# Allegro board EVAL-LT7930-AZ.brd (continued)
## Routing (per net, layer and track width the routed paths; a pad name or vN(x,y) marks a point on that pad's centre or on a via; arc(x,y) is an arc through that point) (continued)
INTVCC_1: length 49.7
  TOP w0.254: U1.9 93.96,164.36 v3(94.36,163.96) ; R25.2 94.53,179.09 94.89,179.09 v3(95,179.2) 95.12,179.07 95.45,179.07 R26.2 ; v3(100.08,169.04) R27.2 ; TP14.1 v3(119.89,171.45)
  TOP w0.381: C21.1 v3(94.36,163.96)
  LAYER_6 w0.254: v3(94.36,163.96) 95.38,164.97 96.27,164.97 96.52,165.23 96.52,167.26 ; v3(95,179.2) 95.63,178.56 95.95,178.56 96.52,177.99 96.52,167.26 ; 96.52,167.26 99.06,167.26 99.44,167.64 99.44,168.4 v3(100.08,169.04) 100.58,169.04 102.43,167.2 113.73,167.2 117.98,171.45 v3(119.89,171.45)
INTVCC_2: length 48.8
  TOP w0.254: R55.2 94.53,90.19 94.89,90.19 v3(95,90.3) 95.12,90.17 95.45,90.17 R56.2 ; U2.9 93.96,75.84 94.36,75.44 v3(94.36,74.99) C54.1 ; TP39.1 v3(119.89,81.92)
  LAYER_6 w0.254: v3(95,90.3) 95.82,90.3 96.46,89.66 96.46,78.23 ; 96.46,78.23 98.87,78.23 99.44,78.8 99.44,79.5 v3(100.08,80.14) 101.09,79.12 114.55,79.12 117.35,81.92 v3(119.89,81.92) ; 96.46,78.23 96.46,76.14 95.76,75.44 94.81,75.44 v3(94.36,74.99)
ITH_1: length 34.4
  TOP w0.254: v3(119.89,184.78) TP10.1 R4.1 ; U1.22 96.87,171.3 97.66,172.09 v3(97.92,172.09) C14.1
  TOP w0.381: R12.1 100.78,173.54 v3(100.77,173.55)
  LAYER_6 w0.254: v3(97.92,172.09) 98.68,172.85 100.2,172.85 100.77,173.42 v3(100.77,173.55) 105.09,173.55 113.79,182.25 117.35,182.25 v3(119.89,184.78)
ITH_2: length 124.6
  TOP w0.254: R4.2 v3(125.6,184.78) ; C47.1 v3(97.92,83.19) 97.66,83.19 96.87,82.4 U2.22 ; TP27.1 v3(119.89,95.25)
  TOP w0.381: R42.1 v3(100.78,84.64)
  LAYER_5 w0.254: v3(119.89,95.25) 119.89,97.79 124.21,102.11 124.21,176.4 126.87,179.07 126.87,183.51 v3(125.6,184.78)
  LAYER_6 w0.254: v3(119.89,95.25) 117.35,95.25 106.93,84.84 100.98,84.84 v3(100.78,84.64) 100.78,84.27 100.46,83.95 98.68,83.95 v3(97.92,83.19)
RUN_1: length 99.3
  TOP w0.254: U1.10 94.46,165 95.38,164.08 C13.1 95.43,163.45 v1(95.89,163.45) 96.34,163.45 R8.2 R7.2 R2.1
  LAYER_4 w0.254: v1(95.89,163.45) 94.74,163.45 94.36,163.07 76.83,163.07 73.03,166.88 63.56,166.88 59.4,162.72 9.05,162.72 TP5.1
RUN_2: length 214.4
  TOP w0.254: C46.1 95.31,74.6 95.31,75.25 94.46,76.1 U2.10 ; v1(98.42,161.8) R2.2
  LAYER_4 w0.254: v1(95.89,74.49) 95.06,74.49 94.74,74.17 77.22,74.17 75.88,72.83 44.26,72.83 9.53,38.1 TP30.1
  LAYER_5 w0.254: v1(95.89,74.49) 96.9,75.5 96.9,84.07 112.01,99.19 112.01,160.53 110.74,161.8 v1(98.42,161.8)
SS_1: length 32.6
  TOP w0.254: U1.20 97.17,170.3 97.28,170.18 v3(97.92,170.18) 98.04,170.05 C11.1 ; R3.1 TP9.1 v3(119.89,180.34)
  LAYER_6 w0.254: v3(97.92,170.18) 98.04,170.18 99.25,171.39 100.9,171.39 101.73,172.21 105.79,172.21 111.38,177.8 117.35,177.8 v3(119.89,180.34)
SS_2: length 122.5
  TOP w0.254: C44.1 98.04,81.15 v3(97.92,81.28) 97.28,81.28 97.17,81.4 U2.20 ; TP26.1 v3(119.82,90.81) ; R3.2 v3(125.6,180.34)
  LAYER_5 w0.254: v3(125.6,180.34) 123.19,177.93 123.19,102.74 118.75,98.3 118.75,91.88 v3(119.82,90.81)
  LAYER_6 w0.254: v3(97.92,81.28) 99.19,82.55 101.09,82.55 102.36,83.82 109.86,83.82 114.94,88.9 117.92,88.9 v3(119.82,90.81)
SYNC_1: length 108.2
  TOP w0.254: U1.30 92.96,173.83 92.96,173.84 v3(92.96,174.37)
  LAYER_4 w0.254: v3(92.96,174.37) 92.08,174.37 88.9,177.55 88.9,180.59 93.09,184.78 106.93,184.78 112.78,178.94 122.05,178.94 125.09,175.9 170.18,175.9 TP7.1
SYNC_2: length 132.1
  TOP w0.254: v3(93.47,89.22) 93.47,89.24 93.46,89.25 R1.2 ; v3(92.96,85.47) 92.96,84.94 92.96,84.93 U2.30
  LAYER_4 w0.254: v3(92.96,85.47) 89.15,89.28 89.15,91.82 93.34,96.01 102.74,96.01 109.35,89.41 126.62,89.41 128.4,87.63 142.75,87.63 160.78,69.6 160.78,60.07 175.13,45.72 TP32.1
  LAYER_5 w0.254: v3(92.96,85.47) 92.4,86.03 92.4,88.91 92.72,89.22 v3(93.47,89.22)
UNNAMED_1_ADLTC7878V2_I139_BG1: length 1.8
  TOP w0.254: 89.77,165.99 89.77,166.09 U1.1
  TOP w0.508: 89.77,165.99 89.28,165.99 88.77,165.48 R10.2
UNNAMED_1_ADLTC7878V2_I139_BG2: length 2.3
  TOP w0.254: U1.12 95.46,165.95 95.48,165.93 95.69,165.93
  TOP w0.508: 95.69,165.93 96.33,165.93 96.9,165.35 R28.2
UNNAMED_1_ADLTC7878V2_I139_BO_1: length 24.4
  TOP w0.254: R79.2 103.96,167.57 103.38,168.15 ; U1.15 97.25,167.79 98.04,167 98.93,167 99.56,167.64 C19.2 100,167.26 103.06,167.26 103.38,167.58 103.38,168.15 ; D8.C 103.38,168.15 ; TP48.1 v3(111,171.45)
  TOP w0.508: v1(100.08,167.39) 99.95,167.39 99.69,167.64 C19.2
  LAYER_4 w0.254: v3(111,171.45) 108.08,171.45 104.65,168.02 102.23,168.02 101.85,167.64 100.33,167.64 v1(100.08,167.39)
UNNAMED_1_ADLTC7878V2_I139_BOOS: length 21.2
  TOP w0.254: R78.2 82.73,165.23 85.2,165.23 85.97,165.99 D5.C 86.61,165.99 ; U1.46 87.71,167.79 C16.1 87.3,166.68 86.61,165.99 ; 86.61,165.99 v1(86.74,165.99) ; TP28.1 v3(75.69,168.91)
  LAYER_4 w0.254: v3(75.69,168.91) 77.6,168.91 80.52,165.99 v1(86.74,165.99)
UNNAMED_1_ADLTC7878V2_I139_CSN: length 6
  TOP w0.254: U1.35 90.46,173.57 89.28,174.75 R29.1 89.21,176.78 TP11.1
UNNAMED_1_ADLTC7878V2_I139_CSP: length 2.4
  TOP w0.254: TP16.1 90.96,175.39 U1.34
UNNAMED_1_ADLTC7878V2_I139_FREQ: length 2.8
  TOP w0.254: R18.1 93.47,175.01 93.96,174.52 U1.28
UNNAMED_1_ADLTC7878V2_I139_IS_1: length 5
  TOP w0.254: U1.43 88.4,169.3 87.88,168.78 86.74,168.78 v3(86.49,168.53) 86.16,168.53 C17.1
  BOTTOM w0.381: v3(86.49,168.53) 86.49,168.85 R17.1 R21.1
UNNAMED_1_ADLTC7878V2_I139_IS_2: length 6.2
  TOP w0.254: 86.13,169.62 C18.1 87.42,169.79 U1.42 ; 86.13,169.62 86.23,169.73 v3(86.23,170.05) ; 86.13,169.62 C17.2 85.07,169.6 R19.2 R13.2
  BOTTOM w0.381: R17.2 86.56,170.05 v3(86.23,170.05)
UNNAMED_1_ADLTC7878V2_I139_ISNS: length 6.9
  TOP w0.254: R23.2 R16.2 85.85,170.81 86.28,171.25 C18.2 ; C18.2 88.2,170.3 U1.41 ; C18.2 v3(87.25,170.69)
  BOTTOM w0.381: v3(87.25,170.69) 87.63,170.31 R21.2
UNNAMED_1_ADLTC7878V2_I139_MODE: length 6.1
  TOP w0.254: U1.26 94.96,173.74 95.5,174.28 v3(95.5,174.82) R22.1 ; R26.1 v3(95.5,177.57)
  LAYER_6 w0.254: v3(95.5,177.57) 95.57,177.51 95.57,174.88 v3(95.5,174.82)
UNNAMED_1_ADLTC7878V2_I139_PGOO: length 28.9
  TOP w0.254: TP15.1 v3(119.89,175.9) ; R27.1 v3(97.92,169.04) 97.66,169.04 96.91,169.79 U1.19
  LAYER_6 w0.254: v3(119.89,175.9) 117.98,175.9 114.55,172.47 110.49,172.47 107.06,169.04 101.98,169.04 101.22,169.8 99.31,169.8 98.55,169.04 v3(97.92,169.04)
UNNAMED_1_ADLTC7878V2_I139_PHAS: length 6.2
  TOP w0.254: v3(94.49,174.82) 94.49,174.88 ; 94.49,174.88 R24.1 ; 94.49,174.88 94.46,174.91 ; 94.46,174.91 94.46,175.11 ; 94.46,174.91 U1.27 ; R25.1 v3(94.49,177.57)
  LAYER_6 w0.254: v3(94.49,177.57) 94.42,177.51 94.42,174.88 v3(94.49,174.82)
UNNAMED_1_ADLTC7878V2_I139_SETC: length 2.6
  TOP w0.254: U1.31 92.46,174.11 92.33,174.24 R20.1
UNNAMED_1_ADLTC7878V2_I139_TG1: length 3.1
  TOP w0.254: U1.47 88.68,167.3 88.27,166.88
  TOP w0.508: 88.27,166.88 88.27,166.24 87.76,165.74 R9.2
UNNAMED_1_ADLTC7878V2_I139_TG2: length 1.8
  TOP w0.254: U1.14 96.86,167.3 97.06,167.1
  TOP w0.508: R30.2 97.35,166.81 97.06,167.1
UNNAMED_1_ADLTC7878V2_I139_VIN: length 2.7
  TOP w0.254: U1.4 91.46,165.19 90.81,164.54 90.81,163.71
UNNAMED_1_ADLTC7878V2_I139_VOUT: length 4.1
  TOP w0.254: R71.1 R70.2 88.23,171.79 U1.38
UNNAMED_1_CAP_I38_N1: length 1
  TOP w0.254: R12.2 C15.1
UNNAMED_1_CAP_I100_N2: length 2
  TOP w0.254: R32.1 88.72,179.71 TP13.1
UNNAMED_1_NCTESTPAD_I113_N1: length 5.3
  TOP w0.254: R35.1 R34.2
  TOP w0.381: R34.2 96.65,178 96.7,178.05 97.35,178.05 99,179.71 TP20.1
UNNAMED_1_RES_I72_N1: length 11.1
  TOP w0.508: 81.28,157.75 81.15,157.88 81.02,157.88 81.02,158.75 v1(81.15,158.88) 82.55,160.27 84.52,160.27 87.76,163.51 R9.1
  BOTTOM w0.508: v1(81.15,158.88) J18.1
UNNAMED_1_RES_I73_N1: length 8.1
  TOP w0.508: 86.36,157.75 86.23,157.88 v1(86.23,158.88) 86.23,160.02 88.77,162.56 R10.1
  BOTTOM w0.508: v1(86.23,158.88) J19.1
UNNAMED_1_RES_I87_N1: length 9.7
  TOP w0.508: R28.1 99.06,165.35 100.84,163.58 v1(100.84,158.88) 100.84,157.88 100.96,157.75
  BOTTOM w0.508: v1(100.84,158.88) J17.1
UNNAMED_1_RES_I115_N1: length 13
  TOP w0.508: R30.1 99.44,166.37 102.49,163.32 102.49,162.31 v1(105.92,158.88) 105.92,157.88 106.04,157.75
  BOTTOM w0.508: J12.1 v1(105.92,158.88)
UNNAMED_2_ADLTC7878V2_I124_BG1: length 2.9
  TOP w0.254: 89.15,76.96 89.96,76.96 U2.1 89.77,77.19 89.77,77.09
  TOP w0.508: R40.2 88.77,76.58 89.28,77.09 89.77,77.09
UNNAMED_2_ADLTC7878V2_I124_BG2: length 2.2
  TOP w0.254: U2.12 95.64,77.01
  TOP w0.508: 95.64,77.01 96.34,77.01 96.9,76.45 R58.2
UNNAMED_2_ADLTC7878V2_I124_BO_1: length 21.7
  TOP w0.254: R80.2 85.23,76.38 D12.C 86.36,77.09 ; U2.46 87.59,78.89 C49.1 87.18,77.91 86.36,77.09 ; 86.36,77.09 v1(86.61,77.09) ; TP49.1 v3(75.06,80.01)
  LAYER_4 w0.254: v1(86.61,77.09) 80.14,77.09 77.22,80.01 v3(75.06,80.01)
UNNAMED_2_ADLTC7878V2_I124_BOOS: length 22.9
  TOP w0.254: v1(100.33,78.49) 100.46,78.61 102.2,78.61 102.96,79.38 D11.C 104.14,79.38 104.52,78.99 104.52,78.92 R81.2 ; C52.2 98.99,78.11 98.04,78.11 97.25,78.89 U2.15 ; TP52.1 v3(111,81.92)
  TOP w0.508: C52.2 99.88,78.49 v1(100.33,78.49)
  LAYER_4 w0.254: v3(111,81.92) 108.08,81.92 104.9,78.74 100.46,78.74 100.33,78.61 v1(100.33,78.49)
UNNAMED_2_ADLTC7878V2_I124_CSN: length 6
  TOP w0.254: U2.35 90.46,84.67 89.28,85.85 R59.1 89.21,87.88 TP53.1
UNNAMED_2_ADLTC7878V2_I124_CSP: length 2.4
  TOP w0.254: U2.34 90.96,86.49 TP41.1
UNNAMED_2_ADLTC7878V2_I124_FREQ: length 2.8
  TOP w0.254: U2.28 93.96,85.62 93.47,86.11 R48.1
UNNAMED_2_ADLTC7878V2_I124_IS_1: length 6.2
  TOP w0.254: 86.13,80.72 86.23,80.83 v3(86.23,81.15) ; 86.13,80.72 C50.2 85.07,80.7 R49.2 R43.2 ; 86.13,80.72 C51.1 87.42,80.89 U2.42
  BOTTOM w0.381: R47.2 86.29,81.21 v3(86.23,81.15)
UNNAMED_2_ADLTC7878V2_I124_IS_2: length 6.9
  TOP w0.254: R53.2 R46.2 85.85,81.92 86.28,82.35 C51.2 ; U2.41 88.2,81.4 C51.2 ; v3(87.25,81.79) C51.2
  BOTTOM w0.508: v3(87.25,81.79) 87.63,81.41 R51.2
UNNAMED_2_ADLTC7878V2_I124_ISNS: length 5
  TOP w0.254: U2.43 88.4,80.4 87.88,79.88 86.74,79.88 v3(86.49,79.63)
  TOP w0.381: v3(86.49,79.63) 86.16,79.63 C50.1
  BOTTOM w0.381: v3(86.49,79.63) 86.49,79.95 R47.1 R51.1
UNNAMED_2_ADLTC7878V2_I124_ITHB: length 6.7
  TOP w0.254: C68.1 v3(97.92,82.17) 97.41,82.17 97.13,81.89 U2.21
  TOP w0.381: R76.1 100.78,81.72 v3(100.77,81.72) 100.78,81.73 R41.2
  LAYER_4 w0.254: v3(97.92,82.17) 99,82.17 99.19,82.36 100.14,82.36 v3(100.77,81.72)
UNNAMED_2_ADLTC7878V2_I124_MODE: length 6.1
  TOP w0.254: R56.1 v3(95.5,88.67) ; U2.26 94.96,84.84 95.5,85.38 v3(95.5,85.92) R52.1
  LAYER_6 w0.254: v3(95.5,85.92) 95.57,85.98 95.57,88.61 v3(95.5,88.67)
UNNAMED_2_ADLTC7878V2_I124_PGOO: length 28.5
  TOP w0.254: TP40.1 v3(119.89,86.36) ; R57.1 v3(97.92,80.14) 97.66,80.14 96.91,80.89 U2.19
  LAYER_6 w0.254: v3(97.92,80.14) 98.55,80.77 100.97,80.77 101.6,80.14 110.87,80.14 115.19,84.45 117.98,84.45 v3(119.89,86.36)
UNNAMED_2_ADLTC7878V2_I124_PHAS: length 6.2
  TOP w0.254: 94.46,86.21 94.46,86.01 ; 94.46,86.01 U2.27 ; 94.46,86.01 94.49,85.98 ; R55.1 v3(94.49,88.67) ; 94.49,85.98 R54.1 ; 94.49,85.98 v3(94.49,85.92)
  LAYER_6 w0.254: v3(94.49,88.67) 94.42,88.61 94.42,85.98 v3(94.49,85.92)
UNNAMED_2_ADLTC7878V2_I124_SETC: length 2.6
  TOP w0.254: U2.31 92.46,85.21 92.33,85.34 R50.1
UNNAMED_2_ADLTC7878V2_I124_TG1: length 3.1
  TOP w0.254: U2.47 88.63,78.4 88.2,77.97
  TOP w0.508: R39.2 87.76,76.96 88.2,77.41 88.2,77.97
UNNAMED_2_ADLTC7878V2_I124_TG2: length 1.8
  TOP w0.254: U2.14 96.86,78.4 97.16,78.11
  TOP w0.508: 97.16,78.11 97.35,77.91 R60.2
UNNAMED_2_ADLTC7878V2_I124_VIN: length 2.7
  TOP w0.254: C45.1 90.93,75.77 91.46,76.29 U2.4
UNNAMED_2_ADLTC7878V2_I124_VOUT: length 4.1
  TOP w0.254: R68.1 R67.2 88.23,82.89 U2.38
UNNAMED_2_CAP_I32_N1: length 1
  TOP w0.381: C48.1 R42.2
UNNAMED_2_CAP_I92_N2: length 2
  TOP w0.254: TP38.1 88.72,90.81 R62.1
UNNAMED_2_NCTESTPAD_I104_N1: length 5.3
  TOP w0.254: R65.1 R64.2
  TOP w0.381: R64.2 96.65,89.1 96.7,89.15 97.35,89.15 99,90.81 TP45.1
UNNAMED_2_RES_I63_N1: length 11
  TOP w0.508: R39.1 87.76,74.55 84.71,71.5 82.68,71.5 v1(81.15,69.98) 81.15,68.98 81.28,68.85
  BOTTOM w0.508: v1(81.15,69.98) J13.1
UNNAMED_2_RES_I64_N1: length 8.1
  TOP w0.508: 86.36,68.85 86.23,68.98 v1(86.23,69.98) 86.23,71.12 88.77,73.66 R40.1
  BOTTOM w0.508: v1(86.23,69.98) J14.1
UNNAMED_2_RES_I106_N1: length 13.1
  TOP w0.508: R60.1 99.57,77.47 102.49,74.55 102.49,73.41 v1(105.92,69.98) 105.92,68.98 106.04,68.85
  BOTTOM w0.508: J16.1 v1(105.92,69.98)
VFB_1: length 28.5
  TOP w0.254: v3(115.44,184.78) TP18.1 R5.1 ; v3(97.98,175.58) 97.97,175.59 R36.1 R35.2 96.52,174.62 95.46,173.57 U1.25
  LAYER_6 w0.254: v3(97.98,175.58) 104.84,175.58 114.05,184.78 v3(115.44,184.78)
VFB_2: length 119
  TOP w0.254: U2.25 95.46,84.67 96.52,85.72 R65.2 R66.1 v3(97.54,85.92) ; R5.2 v3(116.2,181.1) ; TP43.1 v3(115.44,95.25)
  LAYER_5 w0.254: v3(115.44,95.25) 117.47,97.28 117.47,98.55 122.17,103.25 122.17,175.13 v3(116.2,181.1)
  LAYER_6 w0.254: v3(115.44,95.25) 112.9,95.25 104.01,86.36 97.98,86.36 v3(97.54,85.92)
VOUT: length 577.7
  TOP w0.254: R68.2 v1(84.96,85.34) ; R33.2 v1(130.81,153.03) ; TP19.1 v1(100.33,183.39) ; R33.1 v1(129.54,153.03) ; R71.2 v1(85.09,174.24) ; TP44.1 v1(100.33,94.49)
  TOP w0.381: R64.1 96.52,90.68 TP44.1 ; R34.1 96.52,179.58 TP19.1
  TOP w0.508: R62.2 v1(90.48,90.75) ; R63.2 v1(130.81,64.14) ; R31.2 v1(91.31,178.56) ; R63.1 v1(129.54,64.14) ; R32.2 v1(90.48,179.65) ; R61.2 v1(91.31,89.66)
  LAYER_6 w0.254: v1(129.54,153.03) 130.05,153.54 130.05,155.32 131.7,156.97 131.7,179.96 124.71,186.94 107.31,186.94 101.98,181.61 93.85,181.61 91.31,179.07 v1(91.31,178.56) ; v4(128.91,161.29) 129.92,162.31 129.92,178.18 122.3,185.8 108.08,185.8 102.87,180.59 94.87,180.59 91.31,177.04 87.88,177.04 v1(85.09,174.24) ; v1(100.33,94.49) 105.16,99.31 122.81,99.31 137.92,84.2 137.92,75.18 v4(140.84,72.26) ; v1(90.48,179.65) 91.13,179.65 93.6,182.12 101.85,182.12 107.19,187.45 124.84,187.45 132.21,180.09 132.21,156.72 130.56,155.07 130.56,153.29 v1(130.81,153.03) ; v1(129.54,64.14) 129.54,64.26 131.32,66.04 131.32,88.39 122.3,97.41 107.19,97.41 102.23,92.46 93.36,92.46 91.31,90.41 v1(91.31,89.66) ; v1(84.96,85.34) 85.98,85.34 88.77,88.14 91.4,88.14 94.57,91.31 103.25,91.31 108.2,96.27 120.78,96.27 130.18,86.87 130.18,73.66 v4(128.91,72.39) ; v1(90.48,90.75) 90.88,90.75 93.1,92.96 102.11,92.96 107.06,97.92 122.43,97.92 131.83,88.52 131.83,65.53 130.81,64.52 v1(130.81,64.14) ; v4(140.84,161.16) 138.18,163.83 138.18,175.64 125.22,188.59 105.54,188.59 v1(100.33,183.39)
  BOTTOM w0.254: R33.1 v1(129.54,153.03) ; R33.2 v1(130.81,153.03)
  BOTTOM w0.508: R63.2 v1(130.81,64.14) ; R63.1 v1(129.54,64.14)
  vias: v1(106.68,149.22) v1(106.81,60.58) v1(107.31,149.22) v1(107.44,60.58) v1(107.77,159.38) v1(107.77,158.12) v1(107.77,156.84) v1(107.77,155.57) v1(107.77,154.31) v1(107.77,153.03) v1(107.77,151.76) v1(107.77,70.48) v1(107.77,69.22) v1(107.77,67.94) v1(107.77,66.67) v1(107.77,65.41) v1(107.77,64.14) v1(107.77,62.87) v1(107.95,149.22) v1(108.08,60.58) v1(108.58,149.22) v1(108.71,60.58) v1(109.22,149.22) v1(109.35,60.58) v1(109.86,149.22) v1(109.98,60.58) v1(110.49,149.22) v1(110.62,60.58) v1(111.12,149.22) v1(111.25,60.58) v1(113.03,149.73) v1(113.03,60.83) v1(113.41,160.66) v1(113.41,71.75) v1(113.67,149.73) v1(113.67,60.83) v1(114.05,160.66) v1(114.05,71.75) v1(114.3,149.73) v1(114.3,60.83) v1(114.68,160.66) v1(114.68,71.75) v1(116.2,149.73) v1(116.2,60.83) v1(116.59,160.66) v1(116.59,71.75) v1(116.84,149.73) v1(116.84,60.83) v1(117.22,160.66) v1(117.22,71.75) v1(117.47,149.73) v1(117.47,60.83) v1(117.86,160.66) v1(117.86,71.75) v1(119.38,149.73) v1(119.38,60.83) v1(119.76,160.66) v1(119.76,71.75) v1(120.02,149.73) v1(120.02,60.83) v1(120.4,160.66) v1(120.4,71.75) v1(120.65,149.73) v1(120.65,60.83) v1(121.03,160.66) v1(121.03,71.75) v1(125.73,155.07) v1(125.73,153.8) v1(125.73,152.53) v1(125.73,151.26) v1(125.73,66.17) v1(125.73,64.9) v1(125.73,63.63) v1(125.73,62.36) v1(127,155.07) v1(127,153.8) v1(127,152.53) v1(127,151.26) v1(127,66.17) v1(127,64.9) v1(127,63.63) v1(127,62.36) v1(133.99,154.94) v1(133.99,153.67) v1(133.99,152.4) v1(133.99,151.13) v1(133.99,66.17) v1(133.99,64.9) v1(133.99,63.63) v1(133.99,62.36) v1(135.25,154.94) v1(135.25,153.67) v1(135.25,152.4) v1(135.25,151.13) v1(135.25,66.17) v1(135.25,64.9) v1(135.25,63.63) v1(135.25,62.36) v2(103.38,156.87) v2(103.38,155.17) v2(103.38,153.31) v2(103.38,67.94) v2(103.38,66.24) v2(103.38,64.38) v2(103.89,156.87) v2(103.89,155.17) v2(103.89,153.31) v2(103.89,67.94) v2(103.89,66.24) v2(103.89,64.38) v2(104.52,156.87) v2(104.52,155.17) v2(104.52,153.31) v2(104.52,67.94) v2(104.52,66.24) v2(104.52,64.38) v2(105.03,156.87) v2(105.03,155.17) v2(105.03,153.31) v2(105.03,67.94) v2(105.03,66.24) v2(105.03,64.38) v2(105.66,156.87) v2(105.66,155.17) v2(105.66,153.31) v2(105.66,67.94) v2(105.66,66.24) v2(105.66,64.38) v2(106.17,156.87) v2(106.17,155.17) v2(106.17,153.31) v2(106.17,67.94) v2(106.17,66.24) v2(106.17,64.38) v4(126.11,161.29) v4(126.11,159.64) v4(126.11,158.12) v4(126.24,148.08) v4(126.24,146.43) v4(126.24,144.91) v4(126.24,72.39) v4(126.24,70.74) v4(126.24,69.22) v4(126.24,59.18) v4(126.24,57.53) v4(126.24,56.01) v4(128.91,159.64) v4(128.91,158.12) v4(128.91,70.74) v4(128.91,69.22) v4(129.03,148.08) v4(129.03,146.43) v4(129.03,144.91) v4(129.03,59.18) v4(129.03,57.53) v4(129.03,56.01) v4(133.99,146.18) v4(133.99,57.28) v4(134.11,160.66) v4(134.11,71.75) v4(134.87,146.18) v4(134.87,57.28) v4(135,160.66) v4(135,71.75) v4(135.76,146.18) v4(135.76,57.28) v4(135.89,160.66) v4(135.89,71.75) v4(137.16,157.48) v4(137.16,152.4) v4(137.16,147.32) v4(137.16,66.04) v4(137.16,60.96) v4(140.84,159.51) v4(140.84,157.99) v4(140.84,148.21) v4(140.84,146.56) v4(140.84,145.03) v4(140.84,70.61) v4(140.84,69.09) v4(140.84,59.31) v4(140.84,57.66) v4(140.84,56.13) v4(142.24,152.4) v4(142.24,66.04) v4(142.24,60.96) v4(143.64,161.16) v4(143.64,159.51) v4(143.64,157.99) v4(143.64,148.21) v4(143.64,146.56) v4(143.64,145.03) v4(143.64,72.26) v4(143.64,70.61) v4(143.64,69.09) v4(143.64,59.31) v4(143.64,57.66) v4(143.64,56.13) v4(147.32,162.56) v4(147.32,157.48) v4(147.32,152.4) v4(147.32,147.32) v4(147.32,142.24) v4(147.32,137.16) v4(147.32,132.08) v4(147.32,127) v4(147.32,121.92) v4(147.32,116.84) v4(147.32,111.76) v4(147.32,106.68) v4(147.32,101.6) v4(147.32,96.52) v4(147.32,91.44) v4(147.32,86.36) v4(147.32,76.2) v4(147.32,71.12) v4(147.32,66.04) v4(147.32,60.96) v4(147.32,55.88) v4(152.4,162.56) v4(152.4,157.48) v4(152.4,152.4) v4(152.4,147.32) v4(152.4,142.24) v4(152.4,137.16) v4(152.4,132.08) v4(152.4,127) v4(152.4,121.92) v4(152.4,116.84) v4(152.4,111.76) v4(152.4,106.68) v4(152.4,101.6) v4(152.4,96.52) v4(152.4,91.44) v4(152.4,86.36) v4(152.4,81.28) v4(152.4,76.2) v4(152.4,71.12) v4(152.4,66.04) v4(152.4,60.96) v4(152.4,55.88) v4(157.48,162.56) v4(157.48,157.48) v4(157.48,152.4) v4(157.48,147.32) v4(157.48,142.24) v4(157.48,137.16) v4(157.48,132.08) v4(157.48,127) v4(157.48,121.92) v4(157.48,116.84) v4(157.48,111.76) v4(157.48,106.68) v4(157.48,101.6) v4(157.48,96.52) v4(157.48,91.44) v4(157.48,86.36) v4(157.48,81.28) v4(157.48,76.2) v4(157.48,71.12) v4(157.48,66.04) v4(157.48,60.96) v4(157.48,55.88) v4(162.56,162.56) v4(162.56,157.48) v4(162.56,152.4) v4(162.56,147.32) v4(162.56,142.24) v4(162.56,137.16) v4(162.56,132.08) v4(162.56,127) v4(162.56,121.92) v4(162.56,116.84) v4(162.56,111.76) v4(162.56,106.68) v4(162.56,101.6) v4(162.56,96.52) v4(162.56,91.44) v4(162.56,86.36) v4(162.56,81.28) v4(162.56,76.2) v4(162.56,71.12) v4(162.56,66.04) v4(162.56,60.96) v4(162.56,55.88) v4(167.64,147.32) v4(167.64,142.24) v4(167.64,137.16) v4(167.64,132.08) v4(167.64,127) v4(167.64,121.92) v4(167.64,116.84) v4(167.64,111.76) v4(167.64,106.68) v4(172.72,147.32) v4(172.72,127) v4(172.72,121.92) v4(172.72,106.68) v4(177.8,127) v4(177.8,121.92)

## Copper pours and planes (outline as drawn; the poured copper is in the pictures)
SGND on TOP (solid shape): 101.22,82.8 100.08,82.8 100.08,80.77 99.19,80.77 99.19,82.55 99.19,83.57 100.08,83.57 101.22,83.57
SGND on TOP: 91.95,177.8 93.85,177.8 93.85,177.16 95.88,177.16 95.89,176.28 91.95,176.28
SGND on TOP: 94.04,73.85 96.71,73.85 96.71,72.96 94.04,72.96
SGND on TOP: 98.9,87.63 100.75,87.63
SGND on TOP: 100.46,176.28 97.16,176.28 97.16,177.55 97.92,177.55 97.92,177.04 100.46,177.04
SGND on TOP: 115.23,171.45 117.18,171.45
SGND on TOP: 96.77,162.81 96.77,161.8 93.98,161.8 93.98,162.81
SGND on TOP: 91.95,88.81 93.85,88.81 93.85,88.26 94.85,88.26 95.14,88.27 95.77,88.26 95.88,88.27 95.89,87.38 91.95,87.38 91.95,88.58
SGND on TOP: 115.23,81.92 117.18,81.92
SGND on TOP: 97.16,88.65 97.92,88.65 97.92,88.14 100.46,88.14 100.46,87.38 98.17,87.38 97.16,87.38
SGND on TOP: 98.9,176.53 100.75,176.53
SGND on TOP: 99.19,169.67 99.19,172.47 101.22,172.47 101.22,171.7 100.08,171.7 100.08,169.67
SGND on BOTTOM: 88.27,74.04 88.27,89.03 103.63,89.03 103.63,74.04
SGND on BOTTOM: 88.27,162.94 88.27,177.93 103.63,177.93 103.63,162.94
SGND on LAYER_2: 79.88,95 79.88,72.14 111.51,72.14 111.51,95
SGND on LAYER_2: 80.01,183.9 80.01,161.54 91.82,161.54 91.82,94.87 97.03,94.87 97.03,161.54 111.38,161.54 111.38,183.9
SGND on LAYER_3: 81.41,180.97 81.41,160.91 104.14,160.91 104.14,180.97
SGND on LAYER_3: 81.41,92.08 81.41,72.01 104.14,72.01 104.14,92.08
SGND on LAYER_4: 88.27,84.07 88.27,79.5 91.69,76.07 97.16,76.07 97.16,84.07
SGND on LAYER_4: 88.27,172.78 88.27,167.39 90.68,164.97 96.39,164.97 97.16,165.74 97.16,172.78
SGND on LAYER_5: 76.2,183.9 76.2,71.75 111.57,71.75 111.57,183.9
SGND on LAYER_6: 96.52,174.69 96.52,165.29 92.27,165.29 88.9,168.66 88.9,174.69
SGND on LAYER_6: 96.39,85.72 96.39,76.33 92.71,76.33 88.77,80.26 88.77,85.72
VIN on TOP (solid shape): 97.79,72.52 97.03,72.52 97.03,73.91 97.79,73.91
VIN on BOTTOM (solid shape): 91.95,62.1 89.53,62.1 89.28,62.36 89.28,68.33 91.95,68.33
VIN on TOP: 90.55,71.63 90.55,61.72 89.15,61.72 89.15,71.5 89.28,71.63
VIN on TOP: 18.41,162.56 78.04,162.56 78.04,157.35 78.17,157.23 81.92,157.23 81.92,156.53 78.23,156.53 78.04,156.34 78.04,155.64 78.17,155.51 81.91,155.51 81.91,152.3 79.38,152.3 79.38,147.32 64.01,147.32 60.2,143.51 40.64,143.51 40.64,74.1 77.98,74.1 77.98,68.39 78.11,68.26 81.79,68.27 81.79,67.63 78.11,67.63 77.98,67.5 77.98,66.67 78.11,66.55 81.79,66.55 81.79,65.91 78.11,65.91 77.98,65.79 77.98,64.96 78.11,64.83 81.79,64.83 81.79,63.44 79.38,63.44 79.38,58.67 62.8,58.67 58.74,54.61 17.78,54.61 17.78,102.87 2.54,102.87 2.54,151.76 18.41,151.76
VIN on TOP: 89.28,160.53 89.15,160.4 89.15,150.62 90.55,150.62 90.55,160.53
VIN on BOTTOM: 91.95,157.1 91.95,151 89.53,151 89.28,151.26 89.28,157.1
VIN on BOTTOM: 18.41,162.56 77.98,162.56 77.98,157.29 81.66,157.29 81.66,156.53 78.17,156.53 78.17,155.45 81.66,155.45 81.66,154.81 78.17,154.81 78.17,153.73 81.66,153.73 81.66,152.72 79.12,152.72 79.12,146.18 73.79,146.18 73.79,147.32 64.01,147.32 60.2,143.51 40.64,143.51 40.64,74.1 77.98,74.1 77.98,68.39 81.66,68.39 81.66,67.63 78.17,67.63 78.17,66.61 81.66,66.61 81.66,65.91 78.17,65.91 78.17,64.83 81.66,64.83 81.66,63.82 79.06,63.82 79.06,57.47 73.6,57.47 73.6,58.61 62.74,58.61 59.42,55.29 40.64,55.24 17.78,55.24 17.78,102.87 2.54,102.87 2.54,151.76 18.41,151.76
VIN on LAYER_2: 90.68,71.25 90.68,61.85 77.85,61.85 77.85,71.25
VIN on LAYER_2: 18.41,162.56 77.98,162.56 77.98,147.32 64.01,147.32 60.2,143.51 40.64,143.51 40.64,73.91 77.98,73.91 77.98,58.67 62.48,58.67 58.42,54.61 17.78,54.61 17.78,102.87 2.54,102.87 2.54,151.76 18.41,151.76
VIN on LAYER_2: 90.68,160.27 90.68,150.88 77.85,150.88 77.85,160.27
VIN on LAYER_7: 63.5,161.29 78.11,161.29 78.11,157.29 81.66,157.29 81.66,156.53 78.11,156.53 78.11,155.51 81.66,155.51 81.66,154.81 78.11,154.81 78.11,153.73 81.66,153.73 81.66,152.78 79.12,152.78 79.12,148.97 63.5,148.97
VIN on LAYER_7: 63.5,72.39 78.11,72.39 78.11,68.39 81.66,68.39 81.66,67.63 78.11,67.63 78.11,66.61 81.66,66.61 81.66,65.91 78.11,65.91 78.11,64.83 81.66,64.83 81.66,63.88 79.12,63.88 79.12,60.33 63.5,60.33
_N4 on TOP: 100.33,171.45 100.33,169.67 101.22,169.67 101.22,171.45
_N10 on TOP: 115.23,175.9 117.18,175.9
_N12 on TOP: 98.04,174.43 98.04,172.72 98.93,172.72 98.93,174.43
_N77 on TOP: 100.52,68.58 100.52,70.23 101.03,70.23 101.41,69.85 101.41,68.58
_N135 on TOP: 115.23,86.49 117.18,86.49
_N140 on TOP (solid shape): 98.93,83.82 98.04,83.82 98.04,85.47 98.17,85.6 98.93,85.6
_N144 on TOP: 82.3,75.69 82.3,74.8 84.58,74.8 84.58,75.69
_N145 on TOP: 102.87,77.85 102.87,76.96 105.16,76.96 105.16,77.85
_N183 on TOP: 102.87,166.75 102.87,165.86 105.16,165.86 105.16,166.75
_N184 on TOP: 82.3,164.59 82.3,163.7 84.58,163.7 84.58,164.59
_N327 on TOP: 84.45,171.32 84.45,170.31 82.93,170.31 82.93,171.32
_N327 on TOP: 84.33,169.93 84.33,169.16 82.93,169.16 82.93,169.93
_N327 on TOP: 79.63,143.13 79.63,130.43 77.22,130.43 77.22,120.91 91.35,120.9 91.35,140.97 87,140.97 87,143.13 83.86,143.13 83.86,142.28 82.75,142.28 82.75,143.13
_N327 on BOTTOM: 79.38,143.13 79.38,130.43 77.22,130.43 77.22,120.91 87.38,120.91 87.38,143.13 83.86,143.13 83.86,142.28 82.75,142.28 82.75,143.13
_N339 on TOP: 84.45,82.42 84.45,81.41 82.8,81.41 82.8,82.42
_N339 on TOP: 79.63,54.23 79.63,41.53 77.22,41.53 77.22,32.01 91.35,32 91.35,52.07 87,52.07 87,54.23 83.77,54.23 83.77,53.31 82.87,53.31 82.87,54.23
_N339 on BOTTOM: 79.38,54.23 79.38,41.53 77.22,41.53 77.22,32.01 87.38,32.01 87.38,54.23 83.77,54.23 83.77,53.31 82.87,53.31 82.87,54.23 ; 1 cut-out
_N377 on TOP: 105.16,62.99 97.85,62.99 97.85,64.71 97.98,64.83 101.54,64.83 101.66,64.96 101.66,65.79 101.54,65.91 98.04,65.91 97.92,66.04 97.92,66.48 98.04,66.61 101.54,66.61 101.66,66.74 101.66,67.5 101.54,67.63 98.04,67.63 97.92,67.75 97.92,68.2 98.04,68.33 101.54,68.33 101.66,68.45 101.66,69.6 105.28,69.6 105.28,68.58 102.87,68.58 102.74,68.45 102.74,67.56 102.87,67.44 106.49,67.44 106.49,66.74 102.87,66.74 102.74,66.61 102.74,65.85 102.87,65.72 106.49,65.73 106.49,65.02 102.87,65.02 102.74,64.9 102.74,63.44 102.93,63.25 105.16,63.25
_N377 on TOP: 97.98,79.44 97.98,78.36 99.06,78.36 99.06,79.44
_N377 on TOP: 97.85,63.06 105.03,63.06 105.03,36.89 111.63,30.29 111.63,17.46 102.74,17.46 102.74,24.7 95.34,32.1 95.34,52.01 97.73,52.01 97.73,62.93
_N377 on TOP: 84.45,83.69 84.45,82.68 82.8,82.68 82.8,83.69
_N377 on TOP: 110.78,86.36 112.74,86.36
_N377 on BOTTOM: 105.16,62.99 98.04,62.99 98.04,64.83 101.66,64.83 101.66,65.91 97.92,65.91 97.92,66.61 101.66,66.61 101.66,67.63 97.92,67.63 97.92,68.45 101.85,68.45 102.36,68.96 102.36,69.6 105.28,69.6 105.28,68.71 105.16,68.58 103,68.58 103,67.44 106.49,67.44 106.49,66.74 103,66.74 103,65.72 106.49,65.72 106.49,65.02 103,65.02 103,63.12 105.16,63.12
_N377 on BOTTOM: 103.12,72.39 107.19,72.39 107.19,68.71 103.12,68.71
_N377 on BOTTOM: 98.17,63.12 105.92,63.12 105.92,36.07 111.76,30.23 111.76,17.53 102.87,17.53 102.87,24.77 95.38,32.26 95.38,44.52 95.49,44.42 95.63,44.39 95.95,44.71 95.63,45.02 95.49,44.99 95.38,44.89 95.38,52.07 98.04,52.07 98.04,62.99
_N377 on LAYER_7: 105.92,62.99 98.04,62.99 98.04,64.83 101.66,64.83 101.66,65.91 97.92,65.91 97.92,66.61 101.66,66.61 101.66,67.63 97.92,67.63 97.92,68.33 101.73,68.33 101.73,69.72 105.28,69.72 105.28,68.58 103,68.58 103,67.44 106.49,67.44 106.49,66.74 103,66.74 103,65.72 106.49,65.72 106.49,64.77 105.92,64.77
_N377 on LAYER_7: 98.04,63.75 98.04,54.74 105.92,54.74 105.92,63.75
_N381 on TOP: 95.34,140.97 95.34,121.19 102.87,113.67 102.87,106.43 111.76,106.43 111.76,119.25 105.16,125.86 105.16,152.02 97.98,152.02 97.85,151.89 97.85,140.97
_N381 on TOP: 84.45,172.59 84.45,171.58 82.93,171.58 82.93,172.59
_N381 on TOP: 105.16,151.89 97.81,151.89 97.81,153.68 97.87,153.73 101.44,153.73 101.58,153.87 101.58,154.71 101.47,154.82 97.91,154.82 97.82,154.92 97.82,155.37 97.92,155.48 101.5,155.48 101.66,155.64 101.66,156.37 101.52,156.52 97.92,156.52 97.82,156.62 97.82,157.08 97.92,157.18 101.68,157.18 101.68,158.51 105.2,158.51 105.2,157.33 102.94,157.33 102.84,157.23 102.84,156.63 102.99,156.48 106.35,156.48 106.5,156.34 106.51,156.34 106.51,155.62 102.96,155.62 102.81,155.46 102.81,154.81 102.91,154.71 106.38,154.71 106.51,154.58 106.51,153.99 106.44,153.92 102.93,153.92 102.7,153.69 102.7,152.65 103.09,152.27 105.16,152.27
_N381 on TOP: 110.78,175.9 112.74,175.9
_N381 on TOP: 100.84,168.78 100.84,167.77 101.98,167.77 101.98,168.78
_N381 on TOP: 98.04,168.4 98.04,167.26 98.93,167.26 98.93,168.4
_N381 on BOTTOM: 103.25,161.29 103.25,157.61 107.19,157.61 107.19,161.29
_N381 on BOTTOM: 95.5,140.97 95.5,121.03 102.87,113.67 102.87,106.43 111.76,106.43 111.76,119.13 105.92,124.97 105.92,152.02 97.98,152.02 97.92,151.96 97.92,140.97
_N381 on BOTTOM: 105.16,151.89 97.92,151.89 97.92,153.73 101.66,153.73 101.66,154.81 97.92,154.81 97.92,155.51 101.66,155.51 101.66,156.53 97.92,156.53 97.92,157.35 102.11,157.35 102.49,157.73 102.49,158.5 105.28,158.5 105.28,157.61 105.16,157.48 103,157.48 103,156.34 106.49,156.34 106.49,155.64 103,155.64 103,154.62 106.49,154.62 106.49,153.92 103,153.92 103,152.02 105.16,152.02
_N381 on LAYER_7: 105.92,151.89 98.04,151.89 98.04,153.73 101.66,153.73 101.66,154.81 97.92,154.81 97.92,155.51 101.66,155.51 101.66,156.53 97.92,156.53 97.92,157.23 101.73,157.23 101.73,158.5 105.28,158.5 105.28,157.48 103,157.48 103,156.34 106.49,156.34 106.49,155.64 103,155.64 103,154.62 106.49,154.62 106.49,153.67 105.92,153.67
_N381 on LAYER_7: 98.04,152.65 98.04,143.64 105.92,143.64 105.92,152.65
_N399 on TOP: 73.32,83.82 75.27,83.82
_N399 on TOP: 84.33,80.01 84.33,78.74 83.44,78.74 83.44,80.01
_N399 on TOP: 85.6,78.87 85.6,77.72 86.49,77.72 86.49,78.87
_N399 on TOP: 79.63,62.99 86.87,62.99 86.87,64.71 86.74,64.83 83.19,64.83 83.06,64.96 83.06,65.79 83.19,65.91 86.74,65.91 86.87,66.04 86.87,66.48 86.74,66.61 83.25,66.61 83.12,66.74 83.12,67.5 83.25,67.63 86.74,67.63 86.87,67.75 86.87,68.2 86.74,68.33 83.31,68.33 83.12,68.52 83.12,70.23 78.23,70.23 78.23,68.52 81.98,68.52 81.98,67.56 81.85,67.44 78.3,67.44 78.23,67.37 78.23,66.8 78.3,66.74 81.85,66.74 81.98,66.61 81.98,65.85 81.85,65.72 78.3,65.72 78.23,65.66 78.23,65.09 78.3,65.02 81.85,65.02 81.98,64.9 81.98,63.44 81.79,63.25 79.63,63.25
_N399 on TOP: 86.74,63.12 87,62.87 87,54.8 83.76,54.8 83.76,55.51 83.76,55.51 82.86,55.51 82.86,54.8 79.63,54.8 79.63,63.12
_N399 on BOTTOM: 83.25,69.47 83.25,68.45 86.74,68.45 86.74,67.63 83.25,67.63 83.25,66.61 86.74,66.61 86.74,65.91 83.25,65.91 83.25,64.77 86.74,64.77 86.74,62.93 79.38,62.93 79.38,63.63 81.85,63.63 81.85,65.02 78.36,65.02 78.36,65.72 81.85,65.72 81.85,66.8 78.36,66.8 78.36,67.44 81.85,67.44 81.85,68.58 78.23,68.58 78.23,69.47
_N399 on BOTTOM: 78.23,72.39 82.42,72.39 82.42,68.71 78.23,68.71
_N399 on BOTTOM: 86.61,63.12 86.74,62.99 86.74,61.98 87.38,61.34 87.38,54.74 83.76,54.74 83.76,55.51 83.76,55.51 82.86,55.51 82.86,54.74 79.38,54.74 79.38,63.12
_N399 on LAYER_7: 86.61,63.12 86.74,62.99 86.74,61.98 87.38,61.34 87.38,54.74 79.38,54.74 79.38,63.12
_N399 on LAYER_7: 83.25,69.6 83.25,68.45 86.74,68.45 86.74,67.63 83.25,67.63 83.25,66.61 86.74,66.61 86.74,65.91 83.25,65.91 83.25,64.77 86.74,64.77 86.74,62.93 79.38,62.93 79.38,65.02 78.36,65.02 78.36,65.72 81.85,65.72 81.85,66.8 78.36,66.8 78.36,67.44 81.85,67.44 81.85,68.58 78.23,68.58 78.23,69.6
_N400 on TOP: 79.63,151.89 86.98,151.89 86.98,153.74 86.92,153.8 83.21,153.8 83.06,153.95 83.06,154.69 83.21,154.84 86.9,154.84 86.98,154.93 86.98,155.42 86.92,155.49 83.27,155.49 83.12,155.64 83.12,156.4 83.26,156.54 86.9,156.54 86.98,156.62 86.98,157.1 86.86,157.23 83.25,157.23 83.12,157.35 83.12,159.13 78.23,159.13 78.23,157.48 78.3,157.42 82.09,157.42 82.09,156.54 81.93,156.38 78.34,156.38 78.23,156.27 78.23,155.7 78.27,155.66 81.92,155.66 82.1,155.47 82.1,154.88 81.87,154.65 78.35,154.65 78.26,154.57 78.26,154.06 78.34,153.98 81.9,153.98 82.17,153.71 82.17,152.54 81.77,152.15 79.63,152.15
_N400 on TOP: 85.72,167.77 85.72,166.62 86.61,166.62 86.61,167.77
_N400 on TOP: 83.82,166.37 83.82,165.48 84.96,165.48 84.96,166.37
_N400 on TOP: 79.63,152.02 79.63,143.51 82.75,143.51 82.75,144.48 83.86,144.48 83.86,143.51 87,143.51 87,151.76 86.74,152.02
_N400 on TOP: 73.95,172.72 75.91,172.72
_N400 on TOP: 84.33,168.91 84.33,167.64 83.44,167.64 83.44,168.91
_N400 on BOTTOM: 78.36,156.34 78.36,155.64 81.85,155.64 81.85,154.62 78.36,154.62 78.36,153.92 81.85,153.92 81.85,152.53 79.38,152.53 79.38,151.83 86.74,151.83 86.74,153.67 83.31,153.67 83.31,154.81 86.74,154.81 86.74,155.51 83.31,155.51 83.31,156.53 86.74,156.53 86.74,157.35 83.31,157.35 83.31,158.37 78.36,158.37 78.36,157.48 81.85,157.48 81.85,156.34
_N400 on BOTTOM: 78.36,161.29 78.36,157.61 82.55,157.61 82.55,161.29
_N400 on BOTTOM: 79.38,152.02 79.38,143.51 82.75,143.51 82.75,143.51 82.75,144.48 83.86,144.48 83.86,143.51 87.38,143.51 87.38,150.24 86.74,150.88 86.74,151.89 86.61,152.02
_N400 on LAYER_7: 83.25,158.43 83.25,157.35 86.74,157.35 86.74,156.53 83.25,156.53 83.25,155.51 86.74,155.51 86.74,154.81 83.25,154.81 83.25,153.67 86.74,153.67 86.74,151.83 79.38,151.83 79.38,153.92 78.36,153.92 78.36,154.62 81.85,154.62 81.85,155.7 78.36,155.7 78.36,156.34 81.85,156.34 81.85,157.48 78.26,157.48 78.26,158.43
_N400 on LAYER_7: 86.61,152.02 86.74,151.89 86.74,150.88 87.38,150.24 87.38,143.64 79.38,143.64 79.38,152.02
DRVCC_1 on TOP: 86.87,164.59 86.87,163.83 84.96,163.83 84.96,164.59
DRVCC_1 on TOP: 100.58,166.62 100.58,165.86 102.62,165.86 102.62,166.62
DRVCC_1 on TOP: 69.59,168.91 71.38,168.91
DRVCC_2 on TOP: 100.58,77.72 100.58,76.96 102.36,76.96 102.36,77.72
DRVCC_2 on TOP: 84.84,75.69 84.84,74.93 86.87,74.93 86.87,75.69
DRVCC_2 on TOP: 68.95,80.01 70.75,80.01
EXTVCC_1 on TOP: 92.71,164.34 92.71,163.07 93.73,163.07 93.73,164.34
EXTVCC_1 on TOP: 69.59,172.72 71.38,172.72
EXTVCC_2 on TOP: 84.71,83.95 84.71,84.71 86.11,84.71 86.11,83.95
EXTVCC_2 on TOP: 68.95,83.82 70.75,83.82
EXTVCC_2 on TOP: 93.03,75.56 93.47,75.56 93.73,75.31 93.73,74.17 92.71,74.17 92.71,75.25
GROUND on TOP: 109.09,160.53 108.97,160.4 108.97,150.62 110.24,150.62 110.24,160.53
GROUND on TOP: 108.97,61.72 108.97,71.5 109.09,71.63 110.11,71.63 110.11,61.72
GROUND on TOP: 1.27,191.13 184.15,191.13 184.15,1.27 1.27,1.27 ; 4 cut-outs
GROUND on BOTTOM: 109.09,157.1 108.97,156.97 108.97,151 111.44,151 111.44,157.1
GROUND on BOTTOM: 109.09,68.2 108.97,68.07 108.97,62.1 111.44,62.1 111.44,68.2
GROUND on BOTTOM: 1.27,191.13 184.15,191.13 184.15,1.27 1.27,1.27 ; 4 cut-outs
GROUND on LAYER_2, LAYER_3, LAYER_4, LAYER_5, LAYER_6, LAYER_7: 1.27,191.13 184.15,191.13 184.15,1.27 1.27,1.27
INTVCC_1 on TOP: 94.11,179.58 95.82,179.58 95.82,178.69 94.11,178.69
INTVCC_1 on TOP: 119.67,171.45 121.63,171.45
INTVCC_2 on TOP: 119.67,81.92 121.63,81.92
INTVCC_2 on TOP: 94.11,90.68 95.82,90.68 95.82,89.79 95.12,89.79 95.12,89.79 94.11,89.79
ITH_1 on TOP: 119.67,184.78 121.63,184.78
ITH_2 on TOP: 119.67,95.25 121.63,95.25
RUN_1 on TOP: 95,163.89 98.62,163.89 98.81,163.7 98.81,163.07 95,163.07
RUN_2 on TOP: 95,74.99 95,74.17 97.79,74.17 97.79,74.8 97.6,74.99
SS_1 on TOP: 119.67,180.34 121.63,180.34
SS_2 on TOP: 119.67,90.81 121.63,90.81
UNNAMED_1_ADLTC7878V2_I139_BO_1 on TOP: 110.78,171.45 112.74,171.45
UNNAMED_1_ADLTC7878V2_I139_BO_1 on TOP: 102.49,168.66 102.49,167.26 105.16,167.26 105.16,168.66
UNNAMED_1_ADLTC7878V2_I139_BOOS on TOP: 86.87,167.77 86.87,165.86 87,165.86 87.76,166.62 87.76,167.77
UNNAMED_1_ADLTC7878V2_I139_BOOS on TOP: 85.47,166.37 85.47,165.48 87,165.48 87,166.37
UNNAMED_1_ADLTC7878V2_I139_BOOS on TOP: 73.95,168.91 75.91,168.91
UNNAMED_1_ADLTC7878V2_I139_CSN on TOP: 86.73,176.78 88.53,176.78
UNNAMED_1_ADLTC7878V2_I139_CSP on TOP: 89.92,177.23 91.69,177.23 91.69,175.13 91.31,174.75 90.68,174.75 90.3,175.13 90.3,176.4 89.92,176.4
UNNAMED_1_ADLTC7878V2_I139_FREQ on TOP: 93.09,174.94 93.09,175.96 93.85,175.96 93.85,174.62 93.41,174.62
UNNAMED_1_ADLTC7878V2_I139_IS_1 on BOTTOM: 86.23,169.42 86.23,168.34 88.01,168.34 88.01,169.42
UNNAMED_1_ADLTC7878V2_I139_IS_2 on TOP: 84.58,170.05 85.98,170.05 86.17,170.24 87.76,170.24 87.76,169.16 85.47,169.16 85.47,168.15 84.58,168.15
UNNAMED_1_ADLTC7878V2_I139_ISNS on TOP: 85.01,170.31 84.98,170.32 84.96,170.36 84.96,172.59 85.98,172.59 85.98,171.7 87.63,171.7 87.76,171.58 87.76,170.75 87.5,170.5 86.04,170.5 85.85,170.31
UNNAMED_1_ADLTC7878V2_I139_PGOO on TOP: 119.67,175.9 121.63,175.9
UNNAMED_1_ADLTC7878V2_I139_PHAS on TOP: 94.11,175.96 94.87,175.96 94.87,174.62 94.42,174.62 94.11,174.94
UNNAMED_1_ADLTC7878V2_I139_VIN on TOP: 89.41,164.08 89.85,164.08 91.31,165.54 91.31,166.12 91.63,166.12 91.63,164.91 91.44,164.72 91.44,163.07 89.41,163.07
UNNAMED_1_ADLTC7878V2_I139_VOUT on TOP: 86.36,174.62 87.25,174.62 87.25,172.85 86.36,172.85
UNNAMED_1_CAP_I38_N1 on TOP: 101.47,173.48 101.47,171.7 102.36,171.7 102.36,173.48
UNNAMED_1_CAP_I100_N2 on TOP: 88.9,177.55 90.68,177.55 90.68,178.44 89.73,178.44 89.73,179.45 88.9,179.45
UNNAMED_1_CAP_I100_N2 on TOP: 86.73,179.71 88.53,179.71
UNNAMED_1_NCTESTPAD_I113_N1 on TOP: 98.9,179.71 100.75,179.71
UNNAMED_1_RES_I72_N1 on TOP: 80.74,157.48 80.74,159.13 81.59,159.13 82,158.72 82,157.48
UNNAMED_1_RES_I73_N1 on TOP: 85.92,157.48 85.92,159.13 86.42,159.13 86.8,158.75 86.8,157.48
UNNAMED_1_RES_I87_N1 on TOP: 100.28,157.47 100.28,159.13 101.03,159.13 101.42,158.74 101.42,157.47
UNNAMED_1_RES_I115_N1 on TOP: 105.35,157.48 105.35,159.13 106.11,159.13 106.49,158.75 106.49,157.48
UNNAMED_2_ADLTC7878V2_I124_BO_1 on TOP: 85.34,77.47 85.34,76.33 86.87,76.33 86.87,77.47
UNNAMED_2_ADLTC7878V2_I124_BO_1 on TOP: 86.74,78.87 86.74,76.83 86.87,76.83 87.63,77.6 87.63,78.87
UNNAMED_2_ADLTC7878V2_I124_BO_1 on TOP: 73.32,80.01 75.27,80.01
UNNAMED_2_ADLTC7878V2_I124_BOOS on TOP: 110.78,81.92 112.74,81.92
UNNAMED_2_ADLTC7878V2_I124_BOOS on TOP: 102.49,79.76 102.49,78.36 105.16,78.36 105.16,79.76
UNNAMED_2_ADLTC7878V2_I124_CSN on TOP: 86.73,87.88 88.53,87.88
UNNAMED_2_ADLTC7878V2_I124_CSP on TOP: 89.92,88.33 91.69,88.33 91.69,86.23 91.31,85.85 90.68,85.85 90.3,86.23 90.3,87.5 89.92,87.5
UNNAMED_2_ADLTC7878V2_I124_FREQ on TOP: 93.09,87.06 93.85,87.06 93.85,85.94 93.85,85.94 93.85,85.72 93.41,85.72 93.09,86.04
UNNAMED_2_ADLTC7878V2_I124_IS_1 on TOP: 86.17,81.34 87.71,81.34 87.76,81.3 87.76,80.3 87.73,80.26 86.74,80.26 86.72,80.26 85.47,80.26 85.47,79.25 84.58,79.25 84.58,81.15 85.98,81.15
UNNAMED_2_ADLTC7878V2_I124_IS_2 on TOP: 84.96,83.69 85.98,83.69 85.98,82.8 87.63,82.8 87.76,82.68 87.76,81.85 87.5,81.6 86.06,81.6 86.04,81.6 85.85,81.41 84.96,81.41
UNNAMED_2_ADLTC7878V2_I124_ISNS on BOTTOM: 86.23,80.52 86.23,79.44 88.01,79.44 88.01,80.52
UNNAMED_2_ADLTC7878V2_I124_ITHB on TOP: 100.33,82.55 100.33,80.77 101.22,80.77 101.22,82.55
UNNAMED_2_ADLTC7878V2_I124_PGOO on TOP: 119.67,86.36 121.63,86.36
UNNAMED_2_ADLTC7878V2_I124_PHAS on TOP: 94.11,87.06 94.87,87.06 94.87,85.72 94.42,85.72 94.11,86.04 94.11,86.82 94.11,86.83
UNNAMED_2_ADLTC7878V2_I124_VIN on TOP: 91.31,77.47 91.63,77.47 91.63,76.01 91.44,75.82 91.44,74.17 89.41,74.17 89.41,75.18 89.85,75.18 91.31,76.64
UNNAMED_2_ADLTC7878V2_I124_VOUT on TOP: 86.36,83.95 86.36,85.72 87.25,85.72 87.25,83.95
UNNAMED_2_CAP_I32_N1 on TOP: 101.47,84.58 101.47,82.8 102.36,82.8 102.36,84.58
UNNAMED_2_CAP_I92_N2 on TOP: 86.73,90.81 88.53,90.81
UNNAMED_2_CAP_I92_N2 on TOP: 88.9,90.55 89.73,90.55 89.73,89.53 90.68,89.53 90.68,88.65 89.92,88.65 88.9,88.65
UNNAMED_2_NCTESTPAD_I104_N1 on TOP: 98.9,90.81 100.75,90.81
UNNAMED_2_NCTESTPAD_I104_N1 on TOP: 96.17,89.41 96.87,89.41 96.9,89.38 96.9,89.03 96.9,87.5 96.14,87.5 96.14,88.04 96.14,89.38
UNNAMED_2_RES_I63_N1 on TOP: 80.84,68.58 80.84,70.23 81.34,70.23 81.72,69.85 81.72,68.58
UNNAMED_2_RES_I64_N1 on TOP: 85.92,68.58 85.92,70.23 86.42,70.23 86.8,69.85 86.8,68.58
UNNAMED_2_RES_I106_N1 on TOP: 105.6,68.58 105.6,70.23 106.11,70.23 106.49,69.85 106.49,68.58
VFB_1 on TOP: 115.23,184.78 117.18,184.78
VFB_1 on TOP: 96.14,175.13 96.14,176.02 98.17,176.02 98.17,175.13
VFB_2 on TOP: 115.23,95.25 117.18,95.25
VFB_2 on TOP: 96.58,85.79 96.14,86.23 96.14,87.12 97.92,87.12 97.92,85.79
VOUT on TOP: 106.81,163.19 106.81,152.02 105.41,152.02 105.41,147.19 121.67,147.19 125.09,143.76 129.92,143.76 129.92,163.19
VOUT on TOP: 106.93,157.61 106.93,151.89 105.54,151.89 105.41,152.02 105.41,152.4 103,152.4 102.9,152.5 102.9,153.68 103.05,153.83 106.53,153.83 106.68,153.98 106.68,154.59 106.45,154.83 102.99,154.83 102.9,154.92 102.9,155.38 102.99,155.47 106.51,155.47 106.66,155.62 106.66,156.3 106.49,156.47 102.92,156.47 102.83,156.55 102.83,157.06 102.94,157.17 106.56,157.17 106.74,157.35 106.74,157.54 106.81,157.61
VOUT on TOP: 98.85,182.88 100.8,182.88
VOUT on TOP: 106.87,68.52 106.87,62.99 105.47,62.99 105.35,63.12 105.35,63.5 103,63.5 102.93,63.56 102.93,64.77 103,64.83 106.49,64.83 106.68,65.02 106.68,65.72 106.49,65.91 103,65.91 102.93,65.98 102.93,66.55 103,66.61 106.49,66.61 106.68,66.8 106.68,67.44 106.49,67.63 103,67.63 102.93,67.69 102.93,68.33 103,68.39 106.68,68.39 106.81,68.52
VOUT on TOP: 98.85,93.98 100.8,93.98
VOUT on TOP: 84.71,84.96 84.71,85.72 86.11,85.72 86.11,84.96
VOUT on TOP: 90.04,89.79 90.04,91.06 90.87,91.06 90.87,89.79
VOUT on TOP: 130.43,163.19 167.13,163.19 167.13,151.76 182.63,151.76 182.63,102.23 167,102.23 167,54.86 130.3,54.86 130.43,54.93 130.43,74.17 130.3,74.3 146.69,74.3 146.69,143.76 130.43,143.76 130.56,143.89 130.56,163.07
VOUT on TOP: 129.67,67.44 129.67,60.83 130.56,60.83 130.56,67.44
VOUT on TOP: 90.04,178.69 90.04,179.96 90.87,179.96 90.87,178.69
VOUT on TOP: 106.81,74.3 106.81,63.12 105.41,63.12 105.41,58.55 121.41,58.55 125.09,54.86 129.79,54.86 129.79,74.3
VOUT on TOP, BOTTOM: 129.79,156.34 129.79,149.73 130.68,149.73 130.68,156.34
VOUT on BOTTOM: 103.12,157.29 107.31,157.29 107.51,157.48 107.51,163.19 129.92,163.19 129.92,143.76 125.09,143.76 121.67,147.19 111.89,147.19 111.89,146.37 106.17,146.37 106.17,152.27 103.12,152.27 103.12,153.73 106.68,153.73 106.68,154.75 103.12,154.75 103.12,155.51 106.68,155.51 106.68,156.53 103.12,156.53
VOUT on BOTTOM: 103.12,68.39 107.25,68.39 107.44,68.58 107.44,74.3 129.92,74.3 129.92,54.86 125.09,54.86 121.41,58.55 111.89,58.55 111.89,57.47 106.17,57.47 106.17,63.37 103.12,63.37 103.12,64.83 106.68,64.83 106.68,65.85 103.12,65.85 103.12,66.61 106.68,66.61 106.68,67.63 103.12,67.63
VOUT on BOTTOM: 130.43,163.19 167.13,163.19 167.13,151.76 182.63,151.76 182.63,102.23 167,102.23 167,54.86 130.43,54.86 130.56,54.99 130.56,74.17 130.43,74.3 146.69,74.3 146.69,143.76 130.43,143.76 130.56,143.89 130.56,163.07
VOUT on BOTTOM: 129.79,67.44 129.79,60.83 130.68,60.83 130.68,67.44
VOUT on LAYER_2: 130.56,163.19 167.13,163.19 167.13,151.76 182.63,151.76 182.63,102.23 167,102.23 167,54.86 130.56,54.86 130.56,74.3 146.69,74.3 146.69,143.76 130.56,143.76
VOUT on LAYER_7: 121.48,72.39 106.68,72.39 106.68,68.39 103.12,68.39 103.12,67.63 106.68,67.63 106.68,66.61 103.12,66.61 103.12,65.91 106.68,65.91 106.68,64.83 103.12,64.83 103.12,63.88 106.17,63.88 106.17,60.33 121.48,60.33
VOUT on LAYER_7: 121.48,161.29 106.68,161.29 106.68,157.29 103.12,157.29 103.12,156.53 106.68,156.53 106.68,155.51 103.12,155.51 103.12,154.81 106.68,154.81 106.68,153.73 103.12,153.73 103.12,152.78 106.17,152.78 106.17,148.84 121.48,148.84

Small or netless copper shapes (teardrops, artwork), in the pictures only: 85 on TOP, 5 on BOTTOM, 6 on LAYER_3, 19 on LAYER_4, 4 on LAYER_5, 45 on LAYER_6

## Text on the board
User.Comments: -THERMAL INTERFACE PAD. T-GLOBAL, TG-A6200-15-15-1.0 | -WASHER, M2 | -Wakefield-Vette, 567-45AB | -SCREW, M2x0.4, 5mm, PAN HEAD, PHILLIPS | HEATSINK HARDWARE (LOCATION P1-P4 & P5-P8): | APPLY THERMAL PAD TO (4x) Q1&Q2, Q3&Q4, Q9&Q10, Q11&Q12 | DO NOT INSTALL
Ref Des/Silkscreen Top: CSNA_2 | ITH_2 | SS_2 | * | EXTVCC | PGND | 36V-65V | SEE USER GUIDE FOR MAX POUT VS. VIN | BUCK-BOOST GAN FET CONTROLLER | PARALLEL DUAL PHASE 4-SWITCH | EVAL-LT7930-AZ
PAGE_OUTLINE: B | C | PER ECR-126252 | PER ECR-129012 | 14JUL25 | 03FEB26 | CCORREA
DIMENSION: FAB NOTES REVISION: 2ND NOVEMBER 2022 | 8.   IMPEDANCE REQUIREMENTS: IF NO STACKUP IS DEFINED, THE VENDOR IS ALLOWED TO ADJUST THE DIELECTRIC | 13.  PLATING SPECIFICATION: | 9.   FILLET OPTIONS TO ENHANCE RELIABILITY AT PAD JUNCTIONS WHERE SPACING PERMITS. | 10.  THIEVING: | 11.  LAYER TO LAYER REGISTRATION SHALL BE WITHIN 0.003 INCHES. | 12.  DRILL SIZES ARE FINISHED HOLE SIZES. ALL HOLES SHALL BE LOCATED WITHIN 0.005 INCHES DTP,UNLESS SPECIFIED. | 14.  SURFACE FINISH: | 15.  SOLDERMASK: | 1.   DIMENSIONS ARE IN INCHES (EXCEPT WHERE NOTED). | ALL DOCUMENTS & SPECIFICATIONS REFERRED TO BELOW SHOULD BE THE LATEST REVISIONS. | 2.  BOARD MATERIAL:(USE CHECKED ITEMS) | 3.   ALL LAMINATES & BONDING MATERIALS SHOULD BE SELECTED FROM IPC-4101 OR IPC-4103,(TG>170 DEGC TD>300 DEGC) | 4.   REFER TO IPC-6010 SERIES, CLASS 2 FOR FABRICATION. | 5.   REFER TO LAMINATION DIAGRAM FOR OVERALL BOARD THICKNESS, TOLERANCE APPLIES AFTER ALL LAMINATION AND PLATING | 6.   BOW & TWIST NOT TO EXCEED 0.0075 INCHES (0.75%) PER LINEAR INCH AND SHOULD BE MEASURED PER IPC-TM-650, METHOD 2.4.22. | 7.   ACCEPTABILITY PER ADI SPECIFICATION TST00115. | 16.  APPLY SILKSCREEN TO BOTH SIDES USING A NON-CONDUCTIVE, EPOXY BASED INK PER ARTWORK. | ( ) FILLETS ALLOWED | (X) FILLETS NOT ALLOWED | ( ) VENDOR MAY ADD THIEVING TO COMPENSATE FOR LOW COPPER DENSITY AREAS MAINTAINING A MINIMUM | (X) VENDOR MAY NOT ADD THIEVING TO COMPENSATE FOR LOW COPPER DENSITY AREAS. | (X) LPI | ( ) OTHER_________ | COLOR | (X) GREEN | (X) WHITE | HINDER PROPER SOLDER WICKING. BARREL RELIEF ON SOLDERMASK ALLOWED IN UNFILLED VIA IN PAD HOLES. | (X) REFER TO LAMINATION DIAGRAM FOR FINISHED COPPER WEIGHT/THICKNESS REQUIRMENTS | (X) IMMERSION GOLD (ENIG) 1.58-3.94 MICRO INCHES OVER 118-236 MICRO INCHES MIN. OF ELECTROLESS NICKEL PER IPC-4552 | ( ) OSP (ORGANIC SOLDERABILITY PRESERVATIVE) | ( ) IMMERSION SILVER | ( ) SOFT WIRE BONDABLE GOLD 30-50 MICRO INCHES OF SOFT WIRE | ( ) EDGE CONNECTOR FINGERS ARE TO BE PLATED WITH 100 MICRO-INCHES(.0001") OF LOW STRESS | THICKNESS & TRACE WIDTHS TO MEET THE IMPEDANCE REQUIREMENT. IF SPECIFIED, THE VENDOR MUST | TRACE WIDTH & SPACING THAT IMPACT THE REQUIREMENTS MUST HAVE WRITTEN APPROVAL FROM ADI. | MINIMUM BARREL PLATING OF 0.001 INCHES. PLATED HOLES SHALL NOT BE ROUGH OR IRREGULAR SO AS TO | SOLDERMASK OVER BARE COPPER OR BARE GOLD (BOTH SIDES) TO MEET IPC-SM-840. | IF PRESENT,DO NOT MODIFY SOLDERMASK DEFINED PADS (MASK OPENINGS LESS THAN COPPER PAD) WITHOUT APPROVAL. | MEET THE REQUIREMENTS LISTED IN THE IMPEDANCE TABLE. ANY ADJUSTMENT MADE TO THE DEFINED STACKUP, | PROCESSES. FINISHED THICKNESS MEASURED FROM TOP COPPER TO BOTTOM COPPER. | (X)  ISOLA 370HR OR S1000-2 OR IT180 OR EQUIVALENT | ( )  ISOLA-FR408HR OR EQUIVALENT | ( )  ISOLA IS410 | ( )  MEGTRON 6 | ( )  NELCO-4000-13 | ( )  ROGERS 4350B | ( ) ROGERS 3003 | ( ) ARLON 85N | ( ) EM370D | ( )  OTHER ________________________ | UL FLAMMABILITY RATING 94V-0. BOARD MATERIAL & CONSTRUCTION SHALL MEET THE REQUIREMENTS OF UL796/UL796F. | BONDABLE GOLD OVER 100-150 MICRO INCHES OF NICKEL | NICKEL UNDER 30 MICRO-INCHES (.0003') OF GOLD | 0.100 INCH CLEARANCE FROM ALL COPPER FEATURES, | THE STARTING COPPER WEIGHT/THICKNESS CAN VARY AS LONG AS THE FINISHED COPPER | WEIGHT/THICKNESS IS NOT LESS THAN THE SPECIFIED VALUE. | UNLESS OTHERWISE SPECIFIED | HOMOGENOUS MATERIALS IN THIS BOARD SHALL BE COMPLAINT WITH THE EU DIRECTIVE 2002/95/EC | . | WORKMANSHIP SHALL CONFORM TO IPC-A-600, CLASS 2. | 21.  INTENTIONAL SHORTS: | 17.  FINAL ELECTRICAL TEST TO BE PERFORMED USING PROVIDED IPC-D-356A NETLIST OR ODB++ FORMAT FILE. | 22.  PEMNUTS: | 23.  MANUFACTURER TO ETCH/STAMP WITH PERMANENT NON-CONDUCTIVE INK | ON SECONDARY SIDE UNLESS OTHERWISE SPECIFIED: | 18.  A TIME DOMAIN REFLECTOMETER REPORT (TDR) FOR EACH IMPEDANCE CONTROLLED LAYER & A CERTIFICATE | 19.  IF PRESENT, ALL BLIND/BURIED VIAS WITH AN ASPECT RATIO <1:1 TO BE PLATED SHUT WITH COPPER WHEN | 20.  FOR VIA FILL INFORMATION REFER TO DRILL CHART: | 25. PANELIZATION: | 27.  MINIMUM DESIGN LINE WIDTH IS .006 INCH. | 28.  MINIMUM DESIGN LINE SPACING IS .006 INCH. | IS ACCEPTABLE, ALL OTHER INSTANCES MUST BE REPORTED. | IF AN INTENTIONAL SHORT REPORT IS SUPPLIED AND DOES NOT MATCH THE FAB DATA THEN | THE PCB SHALL HAVE A VERIFICATION STAMP. | (X)  NON-CONDUCTIVE EPOXY FILL ALL VIA IN PAD DRILLED VIAS | ( )  COPPER FILL ALL 0.XXXX INCHES DRILLED VIAS | ( ) PEMNUTS TO BE INSTALLED BY FABRICATOR | ( ) PEMNUTS NOT TO BE INSTALLED BY FABRICATOR | (X) NOT APPLICABLE | USED AS VIA-IN-PAD OR AS A STACKED VIA. BLIND/BURIED VIAS WITH AN ASPECT RATIO >1:1 TO BE FILLED | A. UL CODE-FLAMMABILITY RATING FOR THOSE APPROVED MATERIALS(IF APPLICABLE) | B. DATE CODE | C. LOT NUMBER | D. MANUFACTURER LOGO | BOARDS TO BE SHIPPED IN ARRAY AND KEPT INTACT | PANEL TO BE SUBJECTED TO CUSTOMERS APPROVAL | PANEL SOLDER PASTE STENCIL GERBER TO BE PROVIDED TO ANALOG | CAN'T BE PERFORMED BECAUSE THE TRACE LENGTH IS TOO SHORT ON THE OUTER LAYERS AT THE PIN ESCAPES | ADI APPROVAL IS REQUIRED. | OF COMPLIANCE SHALL BE PROVIDED BY VENDOR AT TIME OF SHIPMENT. INSTANCES WHERE TDR TESTING | WITH NON-CONDUCTIVE EPOXY. | TOOLING: | FINISH: | NOTES: | MATERIAL: | TESTING: | MISCELLANEOUS: | "0"
User.24: IN | OUT | SUPPLY | POWER | V | I | LOAD | A | - | +
User.45: FIGURE | SIZE | 6.0 | 8.0 | 10.0 | 12.0 | 70.0 | 200.0 | 118.0 | 187.0 | PLATED | NON-PLATED | DRILL CHART: TOP to BOTTOM | ALL UNITS ARE IN MILS | QTY | 88 | 272 | 571 | 1157 | 15 | 8 | 4 | TOLERANCE/NOTES
